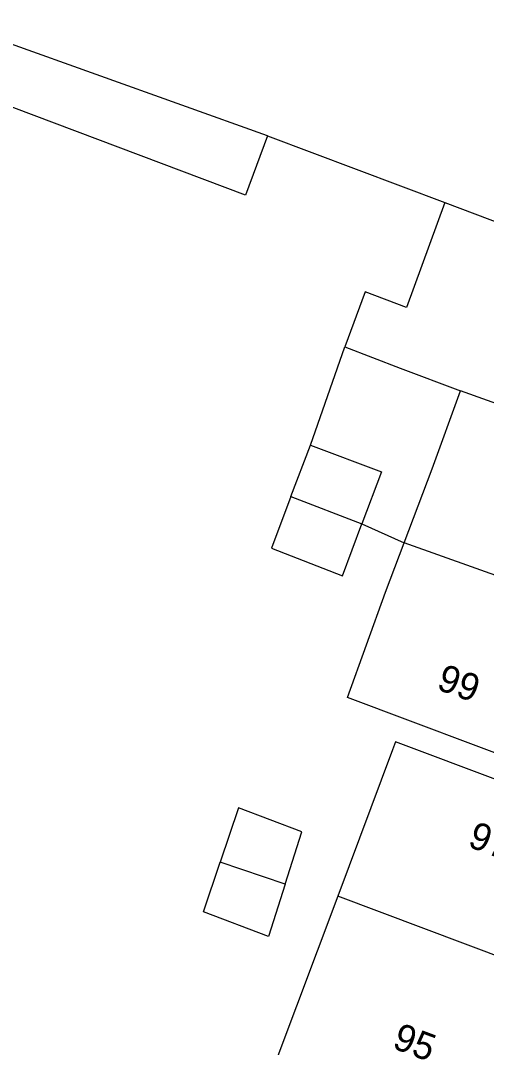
# Model space of a CAD drawing. Extents: x 192672 to 192910, y 446344 to 446512.
# Drawn here: x 192813.76 to 192830.88, y 446414.08 to 446451.8 of the extents above; entities that cross this region are included whole.
import ezdxf

# ---------------------------------------------------------------- set-up
doc = ezdxf.new("R2010")
doc.units = 0
for name, color, linetype in [('huisnummerreeks BGT', 7, 'Continuous'), ('Luifel', 7, 'Continuous'), ('pand op maaiveld vlak', 7, 'Continuous')]:
    doc.layers.add(name, color=color, linetype=linetype)

msp = doc.modelspace()

# ---------------------------------------------------------------- linework, layer by layer
at = {"layer": 'Luifel'}
for p, q in [((192824.406, 446436.208), (192825.677, 446439.814)), ((192826.303, 446433.31), (192827.856, 446432.619))]:
    msp.add_line(p, q, dxfattribs=at)
at = {"layer": 'pand op maaiveld vlak'}
for p, q in [((192822.832, 446447.565), (192829.348, 446445.115)), ((192836.921, 446435.689), (192829.917, 446438.195)), ((192823.695, 446434.314), (192824.406, 446436.208)), ((192823.695, 446434.314), (192826.303, 446433.31)), ((192834.902, 446430.082), (192827.856, 446432.619)), ((192823.485, 446420.072), (192821.091, 446420.878)), ((192833.275, 446416.68), (192825.41, 446419.628))]:
    msp.add_line(p, q, dxfattribs=at)
for points in [[(192822.832, 446447.565), (192813.388, 446450.95), (192811.054, 446451.801)], [(192822.832, 446447.565), (192822.026, 446445.384), (192818.939, 446446.545), (192812.653, 446448.909), (192811.905, 446449.19)], [(192829.348, 446445.115), (192827.942, 446441.255), (192826.414, 446441.835), (192825.677, 446439.814)], [(192829.348, 446445.115), (192832.102, 446444.08), (192838.693, 446441.612)], [(192825.677, 446439.814), (192827.703, 446439.028), (192829.917, 446438.195)], [(192827.856, 446432.619), (192828.885, 446435.328), (192829.917, 446438.195)], [(192824.406, 446436.208), (192827.023, 446435.225), (192826.303, 446433.31)], [(192823.695, 446434.314), (192822.984, 446432.42), (192825.584, 446431.396), (192826.303, 446433.31)], [(192834.902, 446430.082), (192832.903, 446424.53), (192832.816, 446424.287), (192825.772, 446426.935), (192827.165, 446430.802), (192827.856, 446432.619)], [(192835.401, 446422.35), (192827.536, 446425.299), (192827.428, 446425.012), (192825.41, 446419.628)], [(192823.485, 446420.072), (192824.099, 446421.995), (192821.766, 446422.885), (192821.091, 446420.878)], [(192823.485, 446420.072), (192822.871, 446418.149), (192820.479, 446419.062), (192821.091, 446420.878)], [(192825.41, 446419.628), (192823.139, 446413.572), (192826.405, 446412.347)]]:
    msp.add_lwpolyline(points, dxfattribs=at)

# ---------------------------------------------------------------- texts
at = {"layer": 'huisnummerreeks BGT'}
for s, rotation, p in [('99', 340.2, (192829.002, 446427.246)), ('97', 339.5, (192830.146, 446421.47)), ('95', 339.5, (192827.374, 446414.066))]:
    msp.add_text(s, height=1, rotation=rotation, dxfattribs=at).set_placement(p)

doc.saveas('drawing.dxf')
